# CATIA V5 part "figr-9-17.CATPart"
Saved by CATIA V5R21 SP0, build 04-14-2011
Part number: Part1
Bounding box of the stored display mesh (mm): x -77.304 to 77.304, y -77.304 to 125.507, z 0 to 125
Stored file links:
  D:\CATIA V5R21 E-RESOURCES\CATIA-V5R21\catia-v5r21-prt\c09-catia-v5r20-prt\c09-catia-v5r21-figr-9-17.CATPart
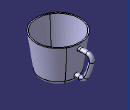
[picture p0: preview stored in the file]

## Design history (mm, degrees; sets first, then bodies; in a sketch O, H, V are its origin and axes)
Set1
  Plane1: type Normal, Curve Sketch3, RefPoint vertex of Sketch3
Body1 (main body)
  Sketch1 on yz-plane, origin (0, 0, 0), H (0, 1, 0), V (0, 0, 1)
    line L1 (0, 0) -> (60, 0)
    point P1 (60, 0)
    point P2 (60, 0)
    line L2 (60, 0) -> (77.5, 125)
    point P3 (77.5, 125)
    line L3 (77.5, 125) -> (0, 125)
    point P4 (0, 125)
    line L4 (0, 125) -> (0, 0)
    axis line L5 (0, 150.2858) -> (0, -31.0593)
    point P5 (0, 150.2858)
    "Radius" P1 L5 = 60
    "Radius" P3 L5 = 77.5
    distance L3 L1 = 125
    horizontal: L1 H, L3 H
    coincidence: P4 V, P2 P1, P5 V
    vertical: L4 V, L5 V
  Shaft1: profile Sketch1, axis Sketch1.L5, angle 360
  Fillet1: radius 15, on edge [face of Shaft1 | face of Shaft1]
  Shell1: ExtOffset 0, Face face of Shaft1, IntOffset 4
  Sketch2 on Plane1, origin (0, 62.9841, 0), H (-1, 0, 0), V (0, 0, 1)
    circle A1 centre (0, 22.002) radius 7.5
    reference projected point E1 (0, 22.002) from vertex of Sketch3
    radius A1 = 7.5
    concentricity: A1 E1
  Sketch3 on yz-plane, origin (0, 0, 0), H (0, 1, 0), V (0, 0, 1)
    line L1 (62.9841, 22.002) -> (78.2172, 22.002)
    arc A1 centre (78.2172, 44.1133) radius 22.1113 from (78.2172, 22.002) to (97.9307, 34.0988) ccw
    arc A2 centre (-112.3295, 140.9107) radius 235.8349 from (97.9307, 34.0988) to (117.8681, 89.6549) ccw
    arc A3 centre (104.0328, 92.7355) radius 14.1742 from (117.8681, 89.6549) to (104.4272, 106.9041) ccw
    arc A4 centre (93.6744, -279.4123) radius 386.4661 from (104.4272, 106.9041) to (82.9216, 106.9041) ccw
    horizontal: L1 H
    tangency: A1 L1, A2 A1, A3 A2, A4 A3
  Rib1: profile Sketch2, centre curve Sketch3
